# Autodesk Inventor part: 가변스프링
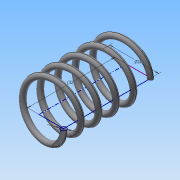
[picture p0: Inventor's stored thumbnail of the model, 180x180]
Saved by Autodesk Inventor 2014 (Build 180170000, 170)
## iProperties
Created: 2017-12
Part Number: 가변스프링
Material: 일반
Document SubType Name: Modeling
Designer: 학생용
Density: 1 g/cm^3
Appearance: 기본값
Mass: 0.86799 g
Surface Area: 17.6846 cm^2
Volume: 0.86799 cm^3
Author: 학생용
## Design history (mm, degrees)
sketch "스케치1"
  geometry: L1 (0, 0)-(9, 0); L2 (9, 0)-(9, -22.583); L3 (9, -22.583)-(0, -22.583); L4 (0, -22.583)-(0, 0); C1 r 1 at (9, 0)
  constraints: 8 end point, 2 parallel, 1 centre point, 1 coincident, 1 horizontal, 1 perpendicular
  dimensions: "d0" = 22.58289 distance of L3.end L1.start (derived); "d1" = 18 diameter of L2 L4; "d2" = 2 diameter of C1
feature "코일1" sketch "스케치1" pitch "d3" = 10; turns "d5" = 5; dims "d4" = 22.58289 (= d0), "d6" = 0, angle "d7" = 90 deg, angle "d8" = 90 deg, "d9" = 0, "d10" = 0
node "작업 평면1"
sketch "스케치2"
  geometry: L1 (8, 0)-(10, 0) reference; 1 further point
  constraints: 1 horizontal alignment
extrude "돌출1" cut sketch "스케치2" distance "d11" = 10; taper "d12" = 0 deg
node "작업 평면2"
sketch "스케치3"
  geometry: L1 (-8, 0)-(-10, 0) reference; 1 further point
  constraints: 1 horizontal alignment
extrude "돌출2" cut sketch "스케치3" distance "d13" = 10; taper "d14" = 0 deg
node "솔리드1"
node "절단 모서리 투영1"
node "절단 모서리 투영2"
